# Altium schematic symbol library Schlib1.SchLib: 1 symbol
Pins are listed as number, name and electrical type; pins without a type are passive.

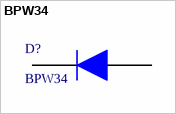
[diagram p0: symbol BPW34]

## BPW34
designator D?
footprint BPW34
footprint BPW34
pins: 1, 2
